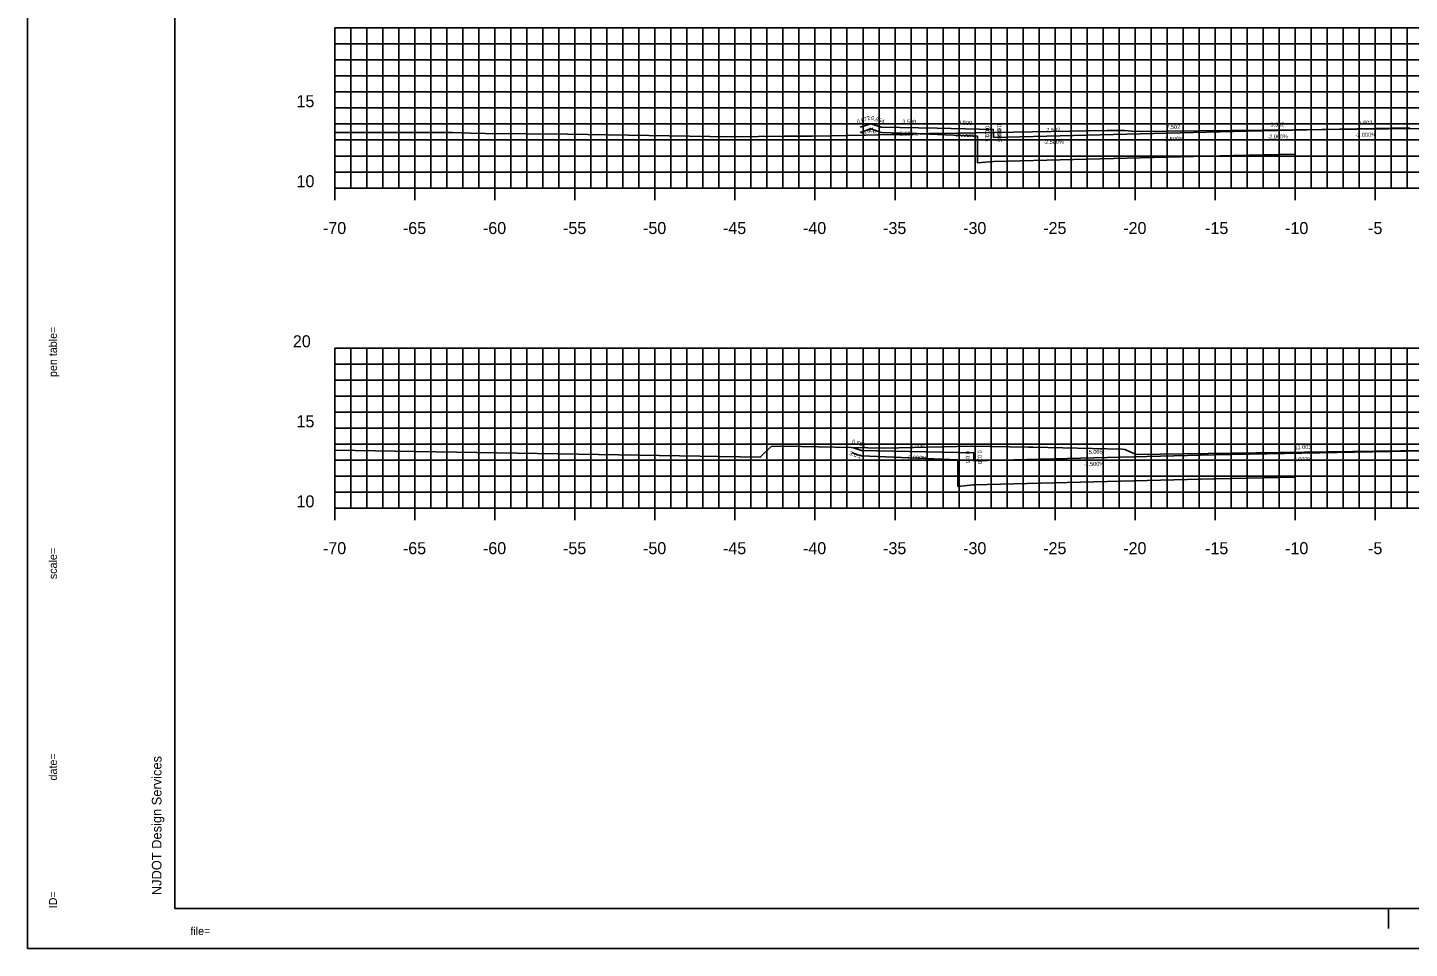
# Model space of a CAD drawing. Extents: x 40011 to 50684, y 49949 to 72236.
# Drawn here: x 42704.8 to 42791.1, y 67867.7 to 67925.2 of the extents above; entities that cross this region are included whole.
import ezdxf

# ---------------------------------------------------------------- set-up
doc = ezdxf.new("R2010")
doc.units = 0
for name, color, linetype in [('1', 7, 'Continuous'), ('10', 7, 'Continuous'), ('41', 7, 'Continuous'), ('51', 7, 'Continuous'), ('52', 7, 'Continuous'), ('53', 7, 'Continuous'), ('54', 7, 'Continuous'), ('55', 7, 'Continuous'), ('57', 7, 'Continuous'), ('58', 7, 'Continuous'), ('59', 7, 'Continuous')]:
    doc.layers.add(name, color=color, linetype=linetype)

msp = doc.modelspace()

# ---------------------------------------------------------------- linework, layer by layer
at = {"layer": '1'}
for p, q in [((42713.985, 67975.196), (42713.985, 67870.196)), ((42713.985, 67870.196), (42878.985, 67870.196)), ((42789.818, 67868.946), (42789.818, 67870.196)), ((42879.485, 67867.696), (42704.79, 67867.696))]:
    msp.add_line(p, q, dxfattribs=at)
at = {"layer": '41'}
for points in [[(42704.79, 67977.696), (42879.485, 67977.696), (42879.485, 67867.696), (42704.79, 67867.696)], [(42713.985, 67975.196), (42878.985, 67975.196), (42878.985, 67870.196), (42713.985, 67870.196)]]:
    msp.add_lwpolyline(points, close=True, dxfattribs=at)
at = {"layer": '51'}
for p, q in [((42723.985, 67915.196), (42723.985, 67925.196)), ((42723.985, 67925.196), (42724.735, 67925.196)), ((42723.985, 67920.196), (42724.735, 67920.196)), ((42723.985, 67915.196), (42724.735, 67915.196)), ((42723.985, 67895.196), (42723.985, 67905.196)), ((42723.985, 67905.196), (42724.735, 67905.196)), ((42723.985, 67900.196), (42724.735, 67900.196)), ((42723.985, 67895.196), (42724.735, 67895.196))]:
    msp.add_line(p, q, dxfattribs=at)
at = {"layer": '52'}
for p, q in [((42723.985, 67915.196), (42863.985, 67915.196)), ((42723.985, 67914.446), (42723.985, 67915.196)), ((42728.985, 67914.446), (42728.985, 67915.196)), ((42733.985, 67914.446), (42733.985, 67915.196)), ((42738.985, 67914.446), (42738.985, 67915.196)), ((42743.985, 67914.446), (42743.985, 67915.196)), ((42748.985, 67914.446), (42748.985, 67915.196)), ((42753.985, 67914.446), (42753.985, 67915.196)), ((42758.985, 67914.446), (42758.985, 67915.196)), ((42763.985, 67914.446), (42763.985, 67915.196)), ((42768.985, 67914.446), (42768.985, 67915.196)), ((42773.985, 67914.446), (42773.985, 67915.196)), ((42778.985, 67914.446), (42778.985, 67915.196)), ((42783.985, 67914.446), (42783.985, 67915.196)), ((42788.985, 67914.446), (42788.985, 67915.196)), ((42723.985, 67895.196), (42863.985, 67895.196)), ((42723.985, 67894.446), (42723.985, 67895.196)), ((42728.985, 67894.446), (42728.985, 67895.196)), ((42733.985, 67894.446), (42733.985, 67895.196)), ((42738.985, 67894.446), (42738.985, 67895.196)), ((42743.985, 67894.446), (42743.985, 67895.196)), ((42748.985, 67894.446), (42748.985, 67895.196)), ((42753.985, 67894.446), (42753.985, 67895.196)), ((42758.985, 67894.446), (42758.985, 67895.196)), ((42763.985, 67894.446), (42763.985, 67895.196)), ((42768.985, 67894.446), (42768.985, 67895.196)), ((42773.985, 67894.446), (42773.985, 67895.196)), ((42778.985, 67894.446), (42778.985, 67895.196)), ((42783.985, 67894.446), (42783.985, 67895.196)), ((42788.985, 67894.446), (42788.985, 67895.196))]:
    msp.add_line(p, q, dxfattribs=at)
at = {"layer": '53'}
for p, q in [((42723.985, 67924.196), (42863.985, 67924.196)), ((42723.985, 67923.196), (42863.985, 67923.196)), ((42723.985, 67922.196), (42863.985, 67922.196)), ((42723.985, 67921.196), (42863.985, 67921.196)), ((42723.985, 67919.196), (42863.985, 67919.196)), ((42723.985, 67918.196), (42863.985, 67918.196)), ((42723.985, 67917.196), (42863.985, 67917.196)), ((42723.985, 67916.196), (42863.985, 67916.196)), ((42723.985, 67904.196), (42863.985, 67904.196)), ((42723.985, 67903.196), (42863.985, 67903.196)), ((42723.985, 67902.196), (42863.985, 67902.196)), ((42723.985, 67901.196), (42863.985, 67901.196)), ((42723.985, 67899.196), (42863.985, 67899.196)), ((42723.985, 67898.196), (42863.985, 67898.196)), ((42723.985, 67897.196), (42863.985, 67897.196)), ((42723.985, 67896.196), (42863.985, 67896.196))]:
    msp.add_line(p, q, dxfattribs=at)
at = {"layer": '54'}
for p, q in [((42724.985, 67915.196), (42724.985, 67925.196)), ((42725.985, 67915.196), (42725.985, 67925.196)), ((42726.985, 67915.196), (42726.985, 67925.196)), ((42727.985, 67915.196), (42727.985, 67925.196)), ((42729.985, 67915.196), (42729.985, 67925.196)), ((42730.985, 67915.196), (42730.985, 67925.196)), ((42731.985, 67915.196), (42731.985, 67925.196)), ((42732.985, 67915.196), (42732.985, 67925.196)), ((42734.985, 67915.196), (42734.985, 67925.196)), ((42735.985, 67915.196), (42735.985, 67925.196)), ((42736.985, 67915.196), (42736.985, 67925.196)), ((42737.985, 67915.196), (42737.985, 67925.196)), ((42739.985, 67915.196), (42739.985, 67925.196)), ((42740.985, 67915.196), (42740.985, 67925.196)), ((42741.985, 67915.196), (42741.985, 67925.196)), ((42742.985, 67915.196), (42742.985, 67925.196)), ((42744.985, 67915.196), (42744.985, 67925.196)), ((42745.985, 67915.196), (42745.985, 67925.196)), ((42746.985, 67915.196), (42746.985, 67925.196)), ((42747.985, 67915.196), (42747.985, 67925.196)), ((42749.985, 67915.196), (42749.985, 67925.196)), ((42750.985, 67915.196), (42750.985, 67925.196)), ((42751.985, 67915.196), (42751.985, 67925.196)), ((42752.985, 67915.196), (42752.985, 67925.196)), ((42754.985, 67915.196), (42754.985, 67925.196)), ((42755.985, 67915.196), (42755.985, 67925.196)), ((42756.985, 67915.196), (42756.985, 67925.196)), ((42757.985, 67915.196), (42757.985, 67925.196)), ((42759.985, 67915.196), (42759.985, 67925.196)), ((42760.985, 67915.196), (42760.985, 67925.196)), ((42761.985, 67915.196), (42761.985, 67925.196)), ((42762.985, 67915.196), (42762.985, 67925.196)), ((42764.985, 67915.196), (42764.985, 67925.196)), ((42765.985, 67915.196), (42765.985, 67925.196)), ((42766.985, 67915.196), (42766.985, 67925.196)), ((42767.985, 67915.196), (42767.985, 67925.196)), ((42769.985, 67915.196), (42769.985, 67925.196)), ((42770.985, 67915.196), (42770.985, 67925.196)), ((42771.985, 67915.196), (42771.985, 67925.196)), ((42772.985, 67915.196), (42772.985, 67925.196)), ((42774.985, 67915.196), (42774.985, 67925.196)), ((42775.985, 67915.196), (42775.985, 67925.196)), ((42776.985, 67915.196), (42776.985, 67925.196)), ((42777.985, 67915.196), (42777.985, 67925.196)), ((42779.985, 67915.196), (42779.985, 67925.196)), ((42780.985, 67915.196), (42780.985, 67925.196)), ((42781.985, 67915.196), (42781.985, 67925.196)), ((42782.985, 67915.196), (42782.985, 67925.196)), ((42784.985, 67915.196), (42784.985, 67925.196)), ((42785.985, 67915.196), (42785.985, 67925.196)), ((42786.985, 67915.196), (42786.985, 67925.196)), ((42787.985, 67915.196), (42787.985, 67925.196)), ((42789.985, 67915.196), (42789.985, 67925.196)), ((42790.985, 67915.196), (42790.985, 67925.196)), ((42724.985, 67895.196), (42724.985, 67905.196)), ((42725.985, 67895.196), (42725.985, 67905.196)), ((42726.985, 67895.196), (42726.985, 67905.196)), ((42727.985, 67895.196), (42727.985, 67905.196)), ((42729.985, 67895.196), (42729.985, 67905.196)), ((42730.985, 67895.196), (42730.985, 67905.196)), ((42731.985, 67895.196), (42731.985, 67905.196)), ((42732.985, 67895.196), (42732.985, 67905.196)), ((42734.985, 67895.196), (42734.985, 67905.196)), ((42735.985, 67895.196), (42735.985, 67905.196)), ((42736.985, 67895.196), (42736.985, 67905.196)), ((42737.985, 67895.196), (42737.985, 67905.196)), ((42739.985, 67895.196), (42739.985, 67905.196)), ((42740.985, 67895.196), (42740.985, 67905.196)), ((42741.985, 67895.196), (42741.985, 67905.196)), ((42742.985, 67895.196), (42742.985, 67905.196)), ((42744.985, 67895.196), (42744.985, 67905.196)), ((42745.985, 67895.196), (42745.985, 67905.196)), ((42746.985, 67895.196), (42746.985, 67905.196)), ((42747.985, 67895.196), (42747.985, 67905.196)), ((42749.985, 67895.196), (42749.985, 67905.196)), ((42750.985, 67895.196), (42750.985, 67905.196)), ((42751.985, 67895.196), (42751.985, 67905.196)), ((42752.985, 67895.196), (42752.985, 67905.196)), ((42754.985, 67895.196), (42754.985, 67905.196)), ((42755.985, 67895.196), (42755.985, 67905.196)), ((42756.985, 67895.196), (42756.985, 67905.196)), ((42757.985, 67895.196), (42757.985, 67905.196)), ((42759.985, 67895.196), (42759.985, 67905.196)), ((42760.985, 67895.196), (42760.985, 67905.196)), ((42761.985, 67895.196), (42761.985, 67905.196)), ((42762.985, 67895.196), (42762.985, 67905.196)), ((42764.985, 67895.196), (42764.985, 67905.196)), ((42765.985, 67895.196), (42765.985, 67905.196)), ((42766.985, 67895.196), (42766.985, 67905.196)), ((42767.985, 67895.196), (42767.985, 67905.196)), ((42769.985, 67895.196), (42769.985, 67905.196)), ((42770.985, 67895.196), (42770.985, 67905.196)), ((42771.985, 67895.196), (42771.985, 67905.196)), ((42772.985, 67895.196), (42772.985, 67905.196)), ((42774.985, 67895.196), (42774.985, 67905.196)), ((42775.985, 67895.196), (42775.985, 67905.196)), ((42776.985, 67895.196), (42776.985, 67905.196)), ((42777.985, 67895.196), (42777.985, 67905.196)), ((42779.985, 67895.196), (42779.985, 67905.196)), ((42780.985, 67895.196), (42780.985, 67905.196)), ((42781.985, 67895.196), (42781.985, 67905.196)), ((42782.985, 67895.196), (42782.985, 67905.196)), ((42784.985, 67895.196), (42784.985, 67905.196)), ((42785.985, 67895.196), (42785.985, 67905.196)), ((42786.985, 67895.196), (42786.985, 67905.196)), ((42787.985, 67895.196), (42787.985, 67905.196)), ((42789.985, 67895.196), (42789.985, 67905.196)), ((42790.985, 67895.196), (42790.985, 67905.196))]:
    msp.add_line(p, q, dxfattribs=at)
at = {"layer": '55'}
for p, q in [((42723.985, 67925.196), (42863.985, 67925.196)), ((42723.985, 67915.196), (42723.985, 67925.196)), ((42728.985, 67915.196), (42728.985, 67925.196)), ((42733.985, 67915.196), (42733.985, 67925.196)), ((42738.985, 67915.196), (42738.985, 67925.196)), ((42743.985, 67915.196), (42743.985, 67925.196)), ((42748.985, 67915.196), (42748.985, 67925.196)), ((42753.985, 67915.196), (42753.985, 67925.196)), ((42758.985, 67915.196), (42758.985, 67925.196)), ((42763.985, 67915.196), (42763.985, 67925.196)), ((42768.985, 67915.196), (42768.985, 67925.196)), ((42773.985, 67915.196), (42773.985, 67925.196)), ((42778.985, 67915.196), (42778.985, 67925.196)), ((42783.985, 67915.196), (42783.985, 67925.196)), ((42788.985, 67915.196), (42788.985, 67925.196)), ((42723.985, 67920.196), (42863.985, 67920.196)), ((42723.985, 67915.196), (42863.985, 67915.196)), ((42723.985, 67905.196), (42863.985, 67905.196)), ((42723.985, 67895.196), (42723.985, 67905.196)), ((42728.985, 67895.196), (42728.985, 67905.196)), ((42733.985, 67895.196), (42733.985, 67905.196)), ((42738.985, 67895.196), (42738.985, 67905.196)), ((42743.985, 67895.196), (42743.985, 67905.196)), ((42748.985, 67895.196), (42748.985, 67905.196)), ((42753.985, 67895.196), (42753.985, 67905.196)), ((42758.985, 67895.196), (42758.985, 67905.196)), ((42763.985, 67895.196), (42763.985, 67905.196)), ((42768.985, 67895.196), (42768.985, 67905.196)), ((42773.985, 67895.196), (42773.985, 67905.196)), ((42778.985, 67895.196), (42778.985, 67905.196)), ((42783.985, 67895.196), (42783.985, 67905.196)), ((42788.985, 67895.196), (42788.985, 67905.196)), ((42723.985, 67900.196), (42863.985, 67900.196)), ((42723.985, 67895.196), (42863.985, 67895.196))]:
    msp.add_line(p, q, dxfattribs=at)
at = {"layer": '57'}
for points in [[(42723.985, 67918.666), (42731.335, 67918.658), (42732.471, 67918.632), (42733.367, 67918.612), (42738.525, 67918.55), (42748.691, 67918.404), (42750.442, 67918.417), (42752.061, 67918.428), (42753.802, 67918.434), (42757.167, 67918.491), (42758.808, 67918.534), (42759.82, 67918.549), (42760.368, 67918.576), (42761.097, 67918.594), (42762.897, 67918.625), (42772.237, 67918.784), (42772.678, 67918.789), (42772.843, 67918.791), (42772.936, 67918.794), (42773.085, 67918.798), (42773.181, 67918.799), (42773.23, 67918.799), (42773.314, 67918.799), (42773.982, 67918.727), (42774.013, 67918.722), (42793.791, 67918.94)], [(42723.985, 67898.828), (42750.571, 67898.376), (42750.588, 67898.397), (42751.254, 67899.057), (42752.098, 67899.063), (42758.33, 67898.944), (42763.749, 67899.071), (42767.324, 67899.009), (42767.613, 67899.003), (42773.174, 67898.875), (42773.335, 67898.871), (42773.352, 67898.864), (42774.048, 67898.547), (42793.557, 67898.826)]]:
    msp.add_lwpolyline(points, dxfattribs=at)
at = {"layer": '58'}
for points in [[(42756.801, 67918.662), (42757.473, 67918.886), (42758.127, 67918.668), (42761.133, 67918.55), (42764.131, 67918.433), (42764.136, 67917.6), (42764.141, 67916.764), (42764.638, 67916.81), (42765.137, 67916.857), (42772.64, 67917.045), (42780.141, 67917.232), (42783.975, 67917.309), (42783.984, 67917.309)], [(42756.32, 67898.653), (42756.671, 67898.535), (42756.9, 67898.459), (42762.904, 67898.224), (42762.914, 67896.557), (42762.914, 67896.555), (42763.895, 67896.646), (42763.91, 67896.648), (42778.915, 67897.023), (42778.942, 67897.023), (42783.985, 67897.125)]]:
    msp.add_lwpolyline(points, dxfattribs=at)
at = {"layer": '59'}
for points in [[(42756.801, 67918.992), (42757.473, 67919.216), (42758.127, 67918.998), (42761.627, 67918.928), (42765.127, 67918.858), (42765.132, 67918.608), (42765.137, 67918.358), (42772.639, 67918.546), (42780.142, 67918.733), (42785.643, 67918.844), (42791.145, 67918.954)], [(42756.32, 67898.983), (42756.9, 67898.789), (42763.9, 67898.649), (42763.91, 67898.149), (42778.915, 67898.524), (42789.918, 67898.744), (42793.985, 67898.826), (42793.985, 67898.826), (42795.743, 67898.799), (42807.449, 67898.565), (42825.946, 67898.103), (42825.956, 67898.603), (42832.956, 67898.743), (42834.415, 67899.229)]]:
    msp.add_lwpolyline(points, dxfattribs=at)

# ---------------------------------------------------------------- texts
at = {"layer": '1'}
for s, height, rotation, p in [('...................pentable..................', 0.0072, 90, (42706.623, 67907.374)), ('pen table=', 0.5, 90, (42706.623, 67903.39)), ('......scale......', 0.0072, 90, (42706.623, 67893.207)), ('scale=', 0.5, 90, (42706.623, 67890.762)), ('.......time......', 0.0072, 90, (42706.623, 67880.374)), ('date=', 0.5, 90, (42706.623, 67878.186)), ('NJDOT Design Services', 0.6, 90, (42713.152, 67871.018)), ('............who............', 0.0072, 90, (42706.623, 67871.529)), ('ID=', 0.5, 90, (42706.623, 67870.2)), ('file=', 0.5, 360, (42714.958, 67868.529)), ('...................bob..................', 0.0072, 360, (42716.623, 67868.529))]:
    msp.add_text(s, height=height, rotation=rotation, dxfattribs=at).set_placement(p)
at = {"layer": '10'}
for s, rotation, p in [('0.672', 18.43495, (42756.641, 67919.203)), ('0.654', 341.56505, (42757.459, 67919.485)), ('3.500', 358.85424, (42759.44, 67919.222)), ('3.500', 358.85424, (42762.94, 67919.152)), ('0.0:1', 271.14576, (42764.622, 67919.084)), ('0.005', 271.14576, (42765.371, 67919.18)), ('7.502', 1.4321, (42775.946, 67918.879)), ('5.502', 1.14576, (42782.448, 67919.03)), ('5.502', 1.14576, (42787.949, 67919.14)), ('-3.0:1', 18.43495, (42756.895, 67918.497)), ('3.0:1', 341.56505, (42757.299, 67918.747)), ('2.000%', 358.85424, (42759.277, 67918.475)), ('2.000%', 358.85424, (42762.777, 67918.405)), ('0.0:1', 271.14576, (42764.627, 67918.834)), ('0.005', 271.14576, (42765.376, 67918.93)), ('-2.500%', 1.4321, (42768.25, 67917.936)), ('7.502', 1.4321, (42768.443, 67918.691)), ('-2.500%', 1.4321, (42775.752, 67918.124)), ('-2.000%', 1.14576, (42782.252, 67918.276)), ('-2.000%', 1.14576, (42787.754, 67918.386)), ('0.580', 341.56505, (42756.27, 67899.263)), ('7.000', 358.85424, (42759.964, 67898.978)), ('11.003', 1.14576, (42783.947, 67898.875)), ('3.0:1', 341.56505, (42756.109, 67898.526)), ('2.000%', 358.85424, (42759.8, 67898.231)), ('0.0:1', 271.14576, (42763.398, 67898.75)), ('0.010', 271.14576, (42764.147, 67898.807)), ('15.005', 1.4321, (42770.903, 67898.574)), ('-2.000%', 1.14576, (42783.776, 67898.122)), ('-2.500%', 1.4321, (42770.774, 67897.821))]:
    msp.add_text(s, height=0.25, rotation=rotation, dxfattribs=at).set_placement(p)
at = {"layer": '51'}
for s, height, p in [('15', 0.75, (42721.592, 67920.246)), ('10', 0.75, (42721.592, 67915.246)), ('-', 0.0001, (42723.985, 67915.196)), ('20', 0.75, (42721.364, 67905.246)), ('15', 0.75, (42721.592, 67900.246)), ('10', 0.75, (42721.592, 67895.246)), ('-', 0.0001, (42723.985, 67895.196))]:
    msp.add_text(s, height=height, dxfattribs=at).set_placement(p)
at = {"layer": '52'}
for s, p in [('-70', (42723.245, 67912.321)), ('-65', (42728.24, 67912.321)), ('-60', (42733.24, 67912.321)), ('-55', (42738.242, 67912.321)), ('-50', (42743.242, 67912.321)), ('-45', (42748.237, 67912.321)), ('-40', (42753.237, 67912.321)), ('-35', (42758.241, 67912.321)), ('-30', (42763.241, 67912.321)), ('-25', (42768.245, 67912.321)), ('-20', (42773.245, 67912.321)), ('-15', (42778.359, 67912.321)), ('-10', (42783.359, 67912.321)), ('-5', (42788.544, 67912.321)), ('-70', (42723.245, 67892.321)), ('-65', (42728.24, 67892.321)), ('-60', (42733.24, 67892.321)), ('-55', (42738.242, 67892.321)), ('-50', (42743.242, 67892.321)), ('-45', (42748.237, 67892.321)), ('-40', (42753.237, 67892.321)), ('-35', (42758.241, 67892.321)), ('-30', (42763.241, 67892.321)), ('-25', (42768.245, 67892.321)), ('-20', (42773.245, 67892.321)), ('-15', (42778.359, 67892.321)), ('-10', (42783.359, 67892.321)), ('-5', (42788.544, 67892.321))]:
    msp.add_text(s, height=0.75, dxfattribs=at).set_placement(p)

doc.saveas('drawing.dxf')
